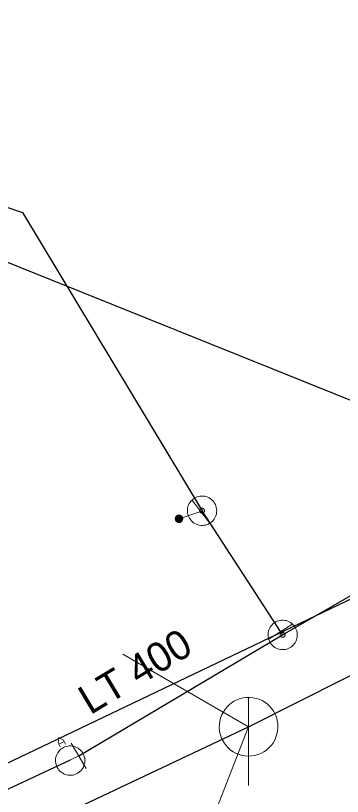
# Model space of a CAD drawing. Extents: x -690535 to -689974, y -975624 to -975325.
# Drawn here: x -690340.48 to -690329.34, y -975480.25 to -975453.68 of the extents above; entities that cross this region are included whole.
import ezdxf

# ---------------------------------------------------------------- set-up
doc = ezdxf.new("R2010")
doc.units = 0
doc.header["$LTSCALE"] = 0.4
for name, color, linetype, lineweight in [('1', 7, 'Continuous', 13), ('11', 7, 'Continuous', 13), ('14', 7, 'Continuous', 25), ('17', 7, 'Continuous', 25), ('22', 7, 'Continuous', 13), ('23', 7, 'Continuous', 13), ('34', 7, 'Continuous', 13), ('47', 7, 'Continuous', 13), ('9', 7, 'Continuous', 13)]:
    doc.layers.add(name, color=color, linetype=linetype, lineweight=lineweight)

msp = doc.modelspace()

# ---------------------------------------------------------------- linework, layer by layer
at = {"layer": '11'}
for p in [(-690336.829, -975475.41), (-690334.41, -975482.64)]:
    msp.add_line(p, (-690332.539, -975477.879), dxfattribs=at)
at = {"layer": '14'}
msp.add_line((-690369.923, -975493.022), (-690316.232, -975467.417), dxfattribs=at)
at = {"layer": '14', "lineweight": 13}
for p, q in [((-690334.166, -975470.558), (-690334.91, -975470.802)), ((-690334.125, -975470.528), (-690334.166, -975470.558)), ((-690331.378, -975474.754), (-690331.456, -975474.64)), ((-690338.608, -975478.999), (-690338.329, -975478.869))]:
    msp.add_line(p, q, dxfattribs=at)
at = {"layer": '14'}
for points in [[(-690360.401, -975454.191), (-690347.831, -975459.234), (-690323.219, -975469.109)], [(-690419.82, -975520.71), (-690394.789, -975508.03), (-690391.289, -975506.52), (-690377.19, -975499.69), (-690356.199, -975489.039), (-690332.539, -975477.879), (-690325.927, -975474.555)]]:
    msp.add_lwpolyline(points, dxfattribs=at)
at = {"layer": '17'}
for p, q in [((-690331.456, -975474.64), (-690334.125, -975470.528)), ((-690338.329, -975478.869), (-690331.378, -975474.754))]:
    msp.add_line(p, q, dxfattribs=at)
for points in [[(-690535.418, -975444.785), (-690534.453, -975442.263), (-690513.173, -975435.01), (-690489.543, -975438.213), (-690462.828, -975441.78), (-690461.125, -975442.127), (-690435.879, -975444.436), (-690407.486, -975446.66), (-690384.232, -975448.792), (-690371.219, -975451.123), (-690363.91, -975452.34), (-690340.249, -975460.384), (-690334.125, -975470.528)], [(-690331.378, -975474.754), (-690325.948, -975471.632), (-690321.744, -975465.274), (-690316.903, -975462.792), (-690313.83, -975458.859), (-690311.528, -975457.668)], [(-690487.124, -975551.552), (-690473.512, -975544.629), (-690473.092, -975544.418), (-690468.651, -975542.14), (-690430.232, -975523.675), (-690404.89, -975511.94), (-690401.289, -975510.34), (-690387.871, -975503.577), (-690350.486, -975484.551), (-690338.608, -975478.999)]]:
    msp.add_lwpolyline(points, dxfattribs=at)
at = {"layer": '22'}
msp.add_line((-690332.539, -975479.879), (-690332.538, -975476.879), dxfattribs=at)
msp.add_lwpolyline([(-690331.539, -975477.879), (-690331.544, -975477.77), (-690331.562, -975477.662), (-690331.592, -975477.556), (-690331.632, -975477.455), (-690331.684, -975477.358), (-690331.746, -975477.268), (-690331.818, -975477.185), (-690331.898, -975477.111), (-690331.986, -975477.045), (-690332.08, -975476.99), (-690332.18, -975476.945), (-690332.285, -975476.912), (-690332.392, -975476.89), (-690332.501, -975476.88), (-690332.611, -975476.882), (-690332.719, -975476.896), (-690332.826, -975476.921), (-690332.929, -975476.958), (-690333.027, -975477.007), (-690333.119, -975477.065), (-690333.205, -975477.134), (-690333.282, -975477.211), (-690333.351, -975477.297), (-690333.41, -975477.389), (-690333.458, -975477.487), (-690333.495, -975477.59), (-690333.521, -975477.697), (-690333.535, -975477.805), (-690333.538, -975477.915), (-690333.528, -975478.024), (-690333.507, -975478.131), (-690333.473, -975478.235), (-690333.429, -975478.335), (-690333.374, -975478.43), (-690333.308, -975478.518), (-690333.234, -975478.598), (-690333.151, -975478.67), (-690333.061, -975478.732), (-690332.965, -975478.784), (-690332.863, -975478.825), (-690332.758, -975478.855), (-690332.65, -975478.873), (-690332.54, -975478.879), (-690332.431, -975478.873), (-690332.323, -975478.855), (-690332.218, -975478.826), (-690332.116, -975478.785), (-690332.019, -975478.733), (-690331.929, -975478.671), (-690331.846, -975478.6), (-690331.771, -975478.52), (-690331.706, -975478.432), (-690331.65, -975478.338), (-690331.606, -975478.238), (-690331.572, -975478.134), (-690331.55, -975478.026), (-690331.54, -975477.917)], close=True, dxfattribs=at)
at = {"layer": '23'}
msp.add_line((-690338.826, -975478.383), (-690339.001, -975478.473), dxfattribs=at)
for points in [[(-690338.957, -975478.559), (-690339.025, -975478.426), (-690339.005, -975478.247), (-690338.85, -975478.337), (-690338.782, -975478.469)], [(-690338.175, -975478.796), (-690338.202, -975478.751), (-690338.234, -975478.708), (-690338.269, -975478.672), (-690338.309, -975478.637), (-690338.351, -975478.607), (-690338.398, -975478.581), (-690338.445, -975478.561), (-690338.495, -975478.546), (-690338.546, -975478.535), (-690338.598, -975478.53), (-690338.651, -975478.53), (-690338.704, -975478.537), (-690338.754, -975478.548), (-690338.803, -975478.565), (-690338.85, -975478.586), (-690338.897, -975478.615), (-690338.937, -975478.645), (-690338.977, -975478.682), (-690339.01, -975478.719), (-690339.041, -975478.762), (-690339.066, -975478.809), (-690339.087, -975478.857), (-690339.102, -975478.908), (-690339.114, -975478.958), (-690339.117, -975479.01), (-690339.116, -975479.063), (-690339.11, -975479.114), (-690339.098, -975479.165), (-690339.081, -975479.215), (-690339.06, -975479.262), (-690339.033, -975479.307), (-690339.002, -975479.35), (-690338.966, -975479.389), (-690338.927, -975479.423), (-690338.884, -975479.451), (-690338.839, -975479.477), (-690338.79, -975479.499), (-690338.74, -975479.514), (-690338.689, -975479.524)], [(-690338.977, -975478.682), (-690339.01, -975478.719), (-690339.041, -975478.762), (-690339.066, -975478.809), (-690339.087, -975478.857), (-690339.102, -975478.908), (-690339.114, -975478.958), (-690339.117, -975479.01), (-690339.116, -975479.063), (-690339.11, -975479.114), (-690339.098, -975479.165), (-690339.081, -975479.215), (-690339.06, -975479.262), (-690339.033, -975479.307), (-690339.002, -975479.35), (-690338.966, -975479.389), (-690338.927, -975479.423), (-690338.884, -975479.451), (-690338.839, -975479.477), (-690338.79, -975479.499), (-690338.74, -975479.514), (-690338.689, -975479.524), (-690338.638, -975479.529), (-690338.584, -975479.528), (-690338.533, -975479.523), (-690338.481, -975479.51), (-690338.433, -975479.493), (-690338.385, -975479.472), (-690338.341, -975479.444), (-690338.298, -975479.414), (-690338.259, -975479.378), (-690338.225, -975479.338), (-690338.195, -975479.295), (-690338.169, -975479.251), (-690338.149, -975479.201), (-690338.133, -975479.152), (-690338.123, -975479.101), (-690338.118, -975479.048), (-690338.119, -975478.996), (-690338.125, -975478.944)], [(-690338.689, -975479.524), (-690338.638, -975479.529), (-690338.584, -975479.528), (-690338.533, -975479.523), (-690338.481, -975479.51), (-690338.433, -975479.493), (-690338.385, -975479.472), (-690338.341, -975479.444), (-690338.298, -975479.414), (-690338.259, -975479.378), (-690338.225, -975479.338), (-690338.195, -975479.295), (-690338.169, -975479.251), (-690338.149, -975479.201), (-690338.133, -975479.152), (-690338.123, -975479.101), (-690338.118, -975479.048), (-690338.119, -975478.996), (-690338.125, -975478.944), (-690338.138, -975478.893), (-690338.154, -975478.844), (-690338.175, -975478.796), (-690338.202, -975478.751), (-690338.234, -975478.708), (-690338.269, -975478.672), (-690338.309, -975478.637), (-690338.351, -975478.607), (-690338.398, -975478.581), (-690338.445, -975478.561), (-690338.495, -975478.546), (-690338.546, -975478.535), (-690338.598, -975478.53), (-690338.651, -975478.53), (-690338.704, -975478.537), (-690338.754, -975478.548), (-690338.803, -975478.565), (-690338.85, -975478.586), (-690338.897, -975478.615), (-690338.937, -975478.645), (-690338.977, -975478.682)], [(-690338.125, -975478.944), (-690338.138, -975478.893), (-690338.154, -975478.844), (-690338.175, -975478.796)]]:
    msp.add_lwpolyline(points, dxfattribs=at)
at = {"layer": '34'}
for p, q in [((-690333.86, -975470.954), (-690334.47, -975470.161)), ((-690331.877, -975474.909), (-690331.034, -975474.371)), ((-690338.584, -975478.439), (-690338.074, -975479.299))]:
    msp.add_line(p, q, dxfattribs=at)
at = {"layer": '47'}
for points in [[(-690333.866, -975470.956), (-690333.823, -975470.926), (-690333.783, -975470.892), (-690333.747, -975470.855), (-690333.715, -975470.814), (-690333.687, -975470.769), (-690333.664, -975470.721), (-690333.647, -975470.673), (-690333.634, -975470.622), (-690333.627, -975470.57), (-690333.625, -975470.518), (-690333.628, -975470.465), (-690333.638, -975470.414), (-690333.652, -975470.364), (-690333.672, -975470.315), (-690333.696, -975470.269), (-690333.726, -975470.226), (-690333.76, -975470.186), (-690333.798, -975470.149), (-690333.838, -975470.118), (-690333.883, -975470.09), (-690333.931, -975470.067), (-690333.98, -975470.049), (-690334.031, -975470.036), (-690334.082, -975470.029), (-690334.134, -975470.028), (-690334.187, -975470.031), (-690334.239, -975470.04), (-690334.288, -975470.055), (-690334.337, -975470.075), (-690334.383, -975470.099), (-690334.426, -975470.129), (-690334.466, -975470.163), (-690334.503, -975470.2), (-690334.534, -975470.241), (-690334.562, -975470.286), (-690334.585, -975470.333), (-690334.604, -975470.382), (-690334.616, -975470.433), (-690334.623, -975470.485), (-690334.624, -975470.537), (-690334.621, -975470.59), (-690334.612, -975470.641), (-690334.597, -975470.691), (-690334.577, -975470.74), (-690334.553, -975470.786), (-690334.523, -975470.829), (-690334.489, -975470.869), (-690334.452, -975470.905), (-690334.411, -975470.937), (-690334.366, -975470.965), (-690334.319, -975470.988), (-690334.27, -975471.006), (-690334.22, -975471.018), (-690334.167, -975471.025), (-690334.115, -975471.027), (-690334.062, -975471.024), (-690334.012, -975471.014), (-690333.961, -975471), (-690333.912, -975470.98)], [(-690334.082, -975470.598), (-690334.074, -975470.593), (-690334.069, -975470.587), (-690334.063, -975470.581), (-690334.057, -975470.575), (-690334.053, -975470.567), (-690334.049, -975470.559), (-690334.046, -975470.551), (-690334.044, -975470.543), (-690334.043, -975470.534), (-690334.043, -975470.526), (-690334.043, -975470.517), (-690334.045, -975470.509), (-690334.047, -975470.501), (-690334.05, -975470.493), (-690334.054, -975470.485), (-690334.059, -975470.477), (-690334.065, -975470.472), (-690334.071, -975470.466), (-690334.077, -975470.46), (-690334.085, -975470.456), (-690334.093, -975470.452), (-690334.101, -975470.449), (-690334.109, -975470.447), (-690334.118, -975470.445), (-690334.126, -975470.446), (-690334.135, -975470.446), (-690334.143, -975470.448), (-690334.151, -975470.45), (-690334.159, -975470.453), (-690334.167, -975470.457), (-690334.175, -975470.462), (-690334.18, -975470.468), (-690334.186, -975470.474), (-690334.192, -975470.48), (-690334.196, -975470.488), (-690334.2, -975470.495), (-690334.203, -975470.504), (-690334.205, -975470.512), (-690334.207, -975470.521), (-690334.206, -975470.529), (-690334.206, -975470.538), (-690334.204, -975470.546), (-690334.202, -975470.554), (-690334.199, -975470.562), (-690334.195, -975470.57), (-690334.19, -975470.578), (-690334.184, -975470.583), (-690334.178, -975470.589), (-690334.172, -975470.595), (-690334.164, -975470.599), (-690334.157, -975470.603), (-690334.148, -975470.606), (-690334.14, -975470.608), (-690334.131, -975470.609), (-690334.123, -975470.609), (-690334.114, -975470.609), (-690334.106, -975470.607), (-690334.098, -975470.605), (-690334.09, -975470.602)], [(-690331.819, -975474.988), (-690331.792, -975475.032), (-690331.761, -975475.075), (-690331.725, -975475.112), (-690331.686, -975475.147), (-690331.643, -975475.177), (-690331.597, -975475.203), (-690331.549, -975475.222), (-690331.499, -975475.238), (-690331.448, -975475.248), (-690331.395, -975475.253), (-690331.343, -975475.252), (-690331.291, -975475.245), (-690331.24, -975475.234), (-690331.191, -975475.217), (-690331.143, -975475.195), (-690331.099, -975475.168), (-690331.056, -975475.137), (-690331.018, -975475.1), (-690330.984, -975475.062), (-690330.954, -975475.019), (-690330.928, -975474.973), (-690330.908, -975474.924), (-690330.892, -975474.874), (-690330.882, -975474.823), (-690330.878, -975474.771), (-690330.879, -975474.719), (-690330.885, -975474.666), (-690330.897, -975474.616), (-690330.914, -975474.567), (-690330.936, -975474.519), (-690330.963, -975474.475), (-690330.994, -975474.432), (-690331.03, -975474.394), (-690331.069, -975474.36), (-690331.112, -975474.33), (-690331.157, -975474.304), (-690331.206, -975474.283), (-690331.256, -975474.268), (-690331.308, -975474.258), (-690331.36, -975474.254), (-690331.412, -975474.255), (-690331.464, -975474.26), (-690331.515, -975474.273), (-690331.564, -975474.29), (-690331.612, -975474.312), (-690331.656, -975474.339), (-690331.699, -975474.37), (-690331.737, -975474.405), (-690331.771, -975474.445), (-690331.801, -975474.488), (-690331.827, -975474.533), (-690331.847, -975474.581), (-690331.862, -975474.631), (-690331.872, -975474.683), (-690331.877, -975474.736), (-690331.876, -975474.788), (-690331.87, -975474.839), (-690331.858, -975474.891), (-690331.841, -975474.94)], [(-690331.45, -975474.792), (-690331.446, -975474.8), (-690331.44, -975474.806), (-690331.435, -975474.812), (-690331.428, -975474.818), (-690331.421, -975474.823), (-690331.413, -975474.827), (-690331.406, -975474.831), (-690331.398, -975474.833), (-690331.389, -975474.834), (-690331.38, -975474.835), (-690331.372, -975474.835), (-690331.363, -975474.834), (-690331.355, -975474.832), (-690331.347, -975474.83), (-690331.339, -975474.826), (-690331.331, -975474.822), (-690331.325, -975474.816), (-690331.319, -975474.811), (-690331.313, -975474.804), (-690331.308, -975474.797), (-690331.304, -975474.789), (-690331.3, -975474.782), (-690331.298, -975474.774), (-690331.296, -975474.765), (-690331.296, -975474.756), (-690331.296, -975474.748), (-690331.297, -975474.739), (-690331.299, -975474.731), (-690331.301, -975474.723), (-690331.305, -975474.715), (-690331.309, -975474.707), (-690331.315, -975474.701), (-690331.32, -975474.695), (-690331.327, -975474.689), (-690331.334, -975474.684), (-690331.341, -975474.68), (-690331.349, -975474.676), (-690331.357, -975474.674), (-690331.366, -975474.672), (-690331.375, -975474.672), (-690331.383, -975474.672), (-690331.392, -975474.673), (-690331.4, -975474.675), (-690331.408, -975474.677), (-690331.416, -975474.681), (-690331.424, -975474.685), (-690331.43, -975474.691), (-690331.436, -975474.696), (-690331.442, -975474.703), (-690331.447, -975474.71), (-690331.451, -975474.717), (-690331.455, -975474.725), (-690331.457, -975474.733), (-690331.458, -975474.742), (-690331.459, -975474.751), (-690331.459, -975474.759), (-690331.458, -975474.768), (-690331.456, -975474.776), (-690331.454, -975474.784)]]:
    msp.add_lwpolyline(points, close=True, dxfattribs=at)
at = {"layer": '9'}
for points in [[(-690335.036, -975470.802), (-690335.036, -975470.815), (-690335.034, -975470.828), (-690335.031, -975470.841), (-690335.026, -975470.853), (-690335.02, -975470.865), (-690335.013, -975470.876), (-690335.005, -975470.886), (-690334.995, -975470.896), (-690334.985, -975470.904), (-690334.974, -975470.911), (-690334.962, -975470.917), (-690334.95, -975470.922), (-690334.937, -975470.925), (-690334.924, -975470.927), (-690334.911, -975470.929), (-690334.898, -975470.928), (-690334.885, -975470.926), (-690334.872, -975470.923), (-690334.86, -975470.918), (-690334.848, -975470.912), (-690334.837, -975470.905), (-690334.827, -975470.897), (-690334.817, -975470.887), (-690334.809, -975470.877), (-690334.802, -975470.866), (-690334.796, -975470.854), (-690334.791, -975470.842), (-690334.788, -975470.829), (-690334.786, -975470.816), (-690334.784, -975470.803), (-690334.785, -975470.79), (-690334.787, -975470.777), (-690334.79, -975470.764), (-690334.795, -975470.752), (-690334.801, -975470.74), (-690334.808, -975470.729), (-690334.816, -975470.719), (-690334.826, -975470.709), (-690334.836, -975470.701), (-690334.847, -975470.694), (-690334.859, -975470.688), (-690334.871, -975470.683), (-690334.884, -975470.68), (-690334.897, -975470.678), (-690334.91, -975470.677), (-690334.923, -975470.677), (-690334.936, -975470.679), (-690334.949, -975470.682), (-690334.961, -975470.687), (-690334.973, -975470.693), (-690334.984, -975470.7), (-690334.994, -975470.708), (-690335.004, -975470.718), (-690335.012, -975470.728), (-690335.019, -975470.739), (-690335.025, -975470.751), (-690335.03, -975470.763), (-690335.033, -975470.776), (-690335.035, -975470.789)], [(-690335.016, -975470.802), (-690335.017, -975470.813), (-690335.015, -975470.824), (-690335.012, -975470.835), (-690335.008, -975470.845), (-690335.003, -975470.855), (-690334.997, -975470.864), (-690334.99, -975470.873), (-690334.982, -975470.881), (-690334.973, -975470.888), (-690334.964, -975470.894), (-690334.954, -975470.899), (-690334.944, -975470.903), (-690334.933, -975470.906), (-690334.922, -975470.909), (-690334.911, -975470.909), (-690334.9, -975470.909), (-690334.889, -975470.907), (-690334.878, -975470.904), (-690334.868, -975470.9), (-690334.858, -975470.895), (-690334.849, -975470.889), (-690334.84, -975470.882), (-690334.832, -975470.874), (-690334.825, -975470.865), (-690334.819, -975470.856), (-690334.814, -975470.846), (-690334.81, -975470.836), (-690334.807, -975470.825), (-690334.805, -975470.814), (-690334.804, -975470.803), (-690334.804, -975470.792), (-690334.806, -975470.781), (-690334.809, -975470.77), (-690334.813, -975470.76), (-690334.818, -975470.75), (-690334.824, -975470.741), (-690334.831, -975470.732), (-690334.839, -975470.724), (-690334.848, -975470.717), (-690334.857, -975470.711), (-690334.867, -975470.706), (-690334.877, -975470.702), (-690334.888, -975470.699), (-690334.899, -975470.697), (-690334.91, -975470.697), (-690334.921, -975470.696), (-690334.932, -975470.698), (-690334.943, -975470.701), (-690334.953, -975470.705), (-690334.963, -975470.71), (-690334.972, -975470.716), (-690334.981, -975470.723), (-690334.989, -975470.731), (-690334.996, -975470.74), (-690335.002, -975470.749), (-690335.007, -975470.759), (-690335.011, -975470.769), (-690335.014, -975470.78), (-690335.016, -975470.791)], [(-690334.997, -975470.802), (-690334.997, -975470.811), (-690334.996, -975470.82), (-690334.993, -975470.829), (-690334.99, -975470.837), (-690334.986, -975470.845), (-690334.981, -975470.853), (-690334.975, -975470.86), (-690334.969, -975470.866), (-690334.962, -975470.872), (-690334.954, -975470.877), (-690334.946, -975470.881), (-690334.938, -975470.884), (-690334.929, -975470.887), (-690334.92, -975470.888), (-690334.911, -975470.89), (-690334.902, -975470.889), (-690334.893, -975470.888), (-690334.884, -975470.885), (-690334.876, -975470.882), (-690334.868, -975470.878), (-690334.86, -975470.873), (-690334.853, -975470.867), (-690334.847, -975470.861), (-690334.841, -975470.854), (-690334.836, -975470.846), (-690334.832, -975470.838), (-690334.829, -975470.83), (-690334.826, -975470.821), (-690334.825, -975470.812), (-690334.823, -975470.803), (-690334.824, -975470.794), (-690334.825, -975470.785), (-690334.828, -975470.776), (-690334.831, -975470.768), (-690334.835, -975470.76), (-690334.84, -975470.752), (-690334.846, -975470.745), (-690334.852, -975470.739), (-690334.859, -975470.733), (-690334.867, -975470.728), (-690334.875, -975470.724), (-690334.883, -975470.721), (-690334.892, -975470.718), (-690334.901, -975470.717), (-690334.91, -975470.716), (-690334.919, -975470.716), (-690334.928, -975470.717), (-690334.937, -975470.72), (-690334.945, -975470.723), (-690334.953, -975470.727), (-690334.961, -975470.732), (-690334.968, -975470.738), (-690334.974, -975470.744), (-690334.98, -975470.751), (-690334.985, -975470.759), (-690334.989, -975470.767), (-690334.992, -975470.775), (-690334.995, -975470.784), (-690334.996, -975470.793)], [(-690334.977, -975470.802), (-690334.977, -975470.809), (-690334.976, -975470.816), (-690334.975, -975470.823), (-690334.972, -975470.829), (-690334.969, -975470.835), (-690334.965, -975470.841), (-690334.961, -975470.847), (-690334.956, -975470.852), (-690334.95, -975470.856), (-690334.944, -975470.86), (-690334.938, -975470.863), (-690334.932, -975470.866), (-690334.925, -975470.867), (-690334.918, -975470.87), (-690334.911, -975470.87), (-690334.904, -975470.87), (-690334.897, -975470.868), (-690334.89, -975470.867), (-690334.884, -975470.864), (-690334.877, -975470.861), (-690334.872, -975470.857), (-690334.866, -975470.853), (-690334.861, -975470.848), (-690334.857, -975470.842), (-690334.853, -975470.836), (-690334.85, -975470.83), (-690334.847, -975470.824), (-690334.845, -975470.817), (-690334.844, -975470.81), (-690334.843, -975470.803), (-690334.843, -975470.796), (-690334.844, -975470.789), (-690334.846, -975470.782), (-690334.849, -975470.776), (-690334.852, -975470.769), (-690334.856, -975470.764), (-690334.86, -975470.758), (-690334.865, -975470.753), (-690334.871, -975470.749), (-690334.876, -975470.745), (-690334.883, -975470.742), (-690334.889, -975470.739), (-690334.896, -975470.737), (-690334.903, -975470.736), (-690334.91, -975470.736), (-690334.917, -975470.736), (-690334.924, -975470.736), (-690334.931, -975470.738), (-690334.937, -975470.741), (-690334.943, -975470.744), (-690334.949, -975470.748), (-690334.955, -975470.752), (-690334.96, -975470.757), (-690334.964, -975470.763), (-690334.968, -975470.768), (-690334.971, -975470.775), (-690334.974, -975470.781), (-690334.975, -975470.788), (-690334.977, -975470.795)], [(-690334.957, -975470.802), (-690334.957, -975470.807), (-690334.957, -975470.812), (-690334.956, -975470.817), (-690334.954, -975470.821), (-690334.952, -975470.826), (-690334.949, -975470.83), (-690334.946, -975470.833), (-690334.942, -975470.837), (-690334.939, -975470.84), (-690334.935, -975470.843), (-690334.93, -975470.845), (-690334.926, -975470.847), (-690334.921, -975470.848), (-690334.916, -975470.85), (-690334.911, -975470.85), (-690334.906, -975470.85), (-690334.901, -975470.849), (-690334.896, -975470.848), (-690334.892, -975470.846), (-690334.887, -975470.844), (-690334.883, -975470.841), (-690334.879, -975470.838), (-690334.876, -975470.834), (-690334.873, -975470.831), (-690334.87, -975470.827), (-690334.868, -975470.822), (-690334.866, -975470.818), (-690334.865, -975470.813), (-690334.864, -975470.808), (-690334.863, -975470.803), (-690334.863, -975470.798), (-690334.864, -975470.793), (-690334.865, -975470.788), (-690334.867, -975470.784), (-690334.869, -975470.779), (-690334.872, -975470.775), (-690334.875, -975470.771), (-690334.878, -975470.768), (-690334.882, -975470.765), (-690334.886, -975470.762), (-690334.891, -975470.76), (-690334.895, -975470.758), (-690334.9, -975470.757), (-690334.905, -975470.756), (-690334.91, -975470.756), (-690334.915, -975470.756), (-690334.92, -975470.757), (-690334.925, -975470.757), (-690334.929, -975470.759), (-690334.934, -975470.761), (-690334.938, -975470.764), (-690334.941, -975470.767), (-690334.945, -975470.77), (-690334.948, -975470.774), (-690334.951, -975470.778), (-690334.953, -975470.783), (-690334.955, -975470.787), (-690334.956, -975470.792), (-690334.957, -975470.797)], [(-690334.937, -975470.802), (-690334.937, -975470.805), (-690334.938, -975470.808), (-690334.937, -975470.81), (-690334.936, -975470.813), (-690334.935, -975470.816), (-690334.933, -975470.818), (-690334.931, -975470.82), (-690334.929, -975470.822), (-690334.927, -975470.824), (-690334.925, -975470.826), (-690334.922, -975470.828), (-690334.919, -975470.829), (-690334.917, -975470.829), (-690334.914, -975470.83), (-690334.911, -975470.83), (-690334.908, -975470.83), (-690334.905, -975470.83), (-690334.902, -975470.829), (-690334.9, -975470.828), (-690334.897, -975470.827), (-690334.895, -975470.825), (-690334.892, -975470.823), (-690334.89, -975470.821), (-690334.889, -975470.819), (-690334.887, -975470.817), (-690334.886, -975470.814), (-690334.884, -975470.811), (-690334.884, -975470.809), (-690334.883, -975470.806), (-690334.882, -975470.803), (-690334.883, -975470.8), (-690334.883, -975470.797), (-690334.884, -975470.794), (-690334.885, -975470.792), (-690334.886, -975470.789), (-690334.888, -975470.787), (-690334.889, -975470.784), (-690334.891, -975470.782), (-690334.894, -975470.781), (-690334.896, -975470.779), (-690334.899, -975470.778), (-690334.901, -975470.777), (-690334.904, -975470.776), (-690334.907, -975470.776), (-690334.91, -975470.775), (-690334.913, -975470.776), (-690334.916, -975470.775), (-690334.918, -975470.777), (-690334.921, -975470.777), (-690334.924, -975470.778), (-690334.926, -975470.78), (-690334.928, -975470.781), (-690334.93, -975470.783), (-690334.932, -975470.786), (-690334.934, -975470.788), (-690334.935, -975470.791), (-690334.936, -975470.793), (-690334.937, -975470.796), (-690334.937, -975470.799)], [(-690334.918, -975470.802), (-690334.918, -975470.804), (-690334.918, -975470.804), (-690334.917, -975470.804), (-690334.917, -975470.806), (-690334.918, -975470.807), (-690334.916, -975470.807), (-690334.916, -975470.807), (-690334.916, -975470.809), (-690334.916, -975470.809), (-690334.915, -975470.81), (-690334.913, -975470.81), (-690334.913, -975470.81), (-690334.913, -975470.811), (-690334.911, -975470.811), (-690334.911, -975470.811), (-690334.91, -975470.811), (-690334.909, -975470.811), (-690334.909, -975470.81), (-690334.908, -975470.81), (-690334.906, -975470.81), (-690334.906, -975470.809), (-690334.906, -975470.809), (-690334.905, -975470.808), (-690334.905, -975470.808), (-690334.903, -975470.807), (-690334.903, -975470.806), (-690334.902, -975470.805), (-690334.902, -975470.805), (-690334.902, -975470.804), (-690334.902, -975470.803), (-690334.902, -975470.802), (-690334.902, -975470.801), (-690334.902, -975470.801), (-690334.903, -975470.8), (-690334.903, -975470.799), (-690334.904, -975470.798), (-690334.904, -975470.798), (-690334.905, -975470.797), (-690334.905, -975470.797), (-690334.906, -975470.796), (-690334.907, -975470.796), (-690334.908, -975470.795), (-690334.908, -975470.795), (-690334.909, -975470.795), (-690334.91, -975470.795), (-690334.911, -975470.795), (-690334.912, -975470.795), (-690334.912, -975470.795), (-690334.913, -975470.796), (-690334.914, -975470.795), (-690334.915, -975470.797), (-690334.915, -975470.797), (-690334.916, -975470.797), (-690334.916, -975470.797), (-690334.917, -975470.799), (-690334.917, -975470.8), (-690334.917, -975470.801), (-690334.918, -975470.801), (-690334.918, -975470.802)]]:
    msp.add_lwpolyline(points, close=True, dxfattribs=at)

# ---------------------------------------------------------------- texts
at = {"layer": '1'}
msp.add_text('LT 400', height=1, rotation=31, dxfattribs=at).set_placement((-690337.937, -975477.491))

doc.saveas('drawing.dxf')
